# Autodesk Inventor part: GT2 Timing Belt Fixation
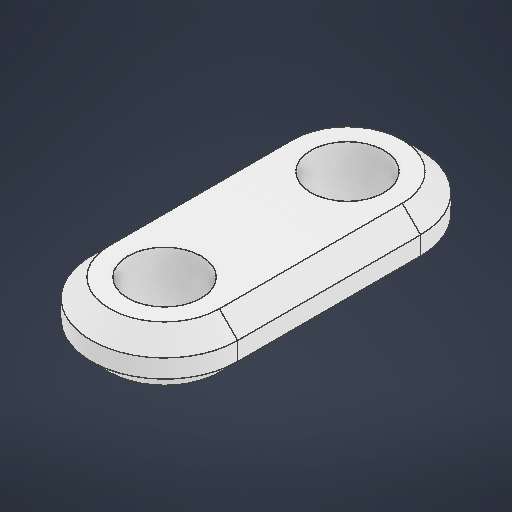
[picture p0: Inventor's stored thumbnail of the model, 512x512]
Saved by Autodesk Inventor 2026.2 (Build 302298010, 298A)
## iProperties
Created: 2026-04
Part Number: GT2 Timing Belt Fixation
Material: ABS 플라스틱
Document SubType Name: Modeling
Designer: work
Density: 1.06 g/cm^3
Appearance: 매끄러움 - 흰색
Author: work
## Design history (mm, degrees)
sketch "스케치1"
  geometry: L1 (0, 0)-(0, -10); L2 (-4, 0)-(-4, -10); L3 (4, -10)-(4, 0); C1 r 2 at (0, 0); C2 r 2 at (0, -10); A1 r 4 centre (0, 0) between (4, 0) and (-4, 0); A2 r 4 centre (0, -10) between (-4, -10) and (4, -10); 1 further point
  constraints: 8 end point, 4 centre point, 4 point on circle, 4 tangent, 2 coincident, 1 midpoint, 1 parallel, 1 vertical
  dimensions: "d0" = 10 distance of L1.start L1.end; "d1" = 8 diameter of A2; "d2" = 4 diameter of C1; "d3" = 4 diameter of C2
extrude "돌출1" new body sketch "스케치1" distance "d4" = 3; taper "d5" = 0 deg
chamfer "모따기1" distance "d6" = 1; stored, may be unused: second distance "d7" = 2, angle "d8" = 45 deg
node "솔리드1"
